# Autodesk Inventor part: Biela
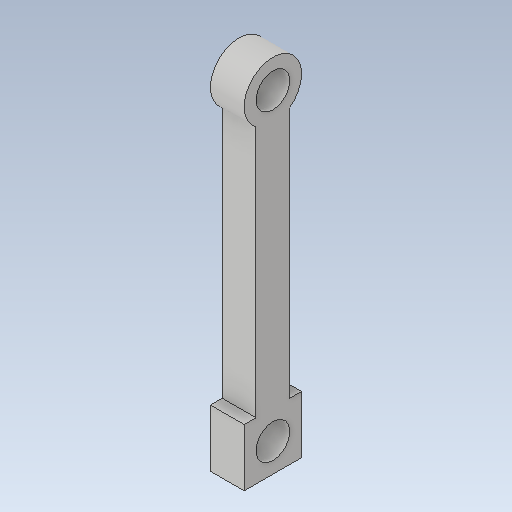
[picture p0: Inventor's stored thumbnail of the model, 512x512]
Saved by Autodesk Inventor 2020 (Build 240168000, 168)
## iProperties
Created: 2019-09
Part Number: Biela
Material: Generic
Document SubType Name: Modeling
Designer: user
Density: 1 g/cm^3
Appearance: Default
Author: user
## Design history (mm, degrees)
sketch "Sketch1"
  geometry: L1 (8.5, 8.5)-(-8.5, 8.5); L2 (-8.5, 8.5)-(-8.5, -8.5); L3 (-8.5, -8.5)-(8.5, -8.5); L4 (84.41, -5)-(8.5, -5); L5 (84.41, 5)-(8.5, 5); L6 (8.5, -8.5)-(8.5, -5); L7 (8.5, 5)-(8.5, 8.5); C1 r 5 at (0, 0); C2 r 5 at (90, 0); A1 r 7.5 centre (90, 0) between (84.41, -5) and (84.41, 5); 4 further points
  constraints: 14 end point, 3 centre point, 3 parallel, 3 perpendicular, 2 coincident, 2 midpoint, 2 point on circle, 1 horizontal, 1 horizontal alignment, 1 tangent, 1 vertical alignment
  dimensions: "d0" = 90 distance of C2.centre point (0, 0); "d1" = 10 diameter of C1; "d3" = 17 distance of L3.end L2.end; "d4" = 17 distance of L2.end L1.end; "d5" = 10 diameter of C2; "d6" = 15 diameter of A1
extrude "Extrusion1" new body sketch "Sketch1" distance "d9" = 10; taper "d10" = 0 deg
sketch "Sketch2"
  geometry: C1 r 5 at (0, 90) reference; C2 r 8.5 at (0, 90); C3 r 6.403 at (0, 90); 1 further point
  constraints: 2 centre point, 2 coincident
  dimensions: "d11" = 17 diameter of C2
extrude "Extrusion2" join sketch "Sketch2" distance "d12" = 10; taper "d13" = 0 deg
body "Solid1"
